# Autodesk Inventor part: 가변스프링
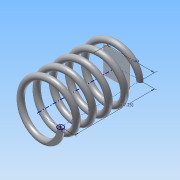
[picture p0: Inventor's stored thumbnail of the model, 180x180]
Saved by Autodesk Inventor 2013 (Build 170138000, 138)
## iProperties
Created: 2018-08
Part Number: 가변스프링
Material: 알루미늄 6061
Document SubType Name: Modeling
Designer: Administrator
Density: 2.71 g/cm^3
Mass: 32.8823 g
Surface Area: 98.6263 cm^2
Volume: 12.1337 cm^3
Author: Administrator
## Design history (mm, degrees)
sketch "스케치1"
  geometry: L1 (0, 0)-(20, 0); L2 (20, 0)-(20, 67.25); L3 (20, 67.25)-(0, 67.25); L4 (0, 67.25)-(0, 0); C1 r 2.5 at (20, 0)
  constraints: 8 end point, 2 parallel, 1 centre point, 1 coincident, 1 horizontal, 1 perpendicular
  dimensions: "d0" = 5 diameter of C1; "d2" = 67.25 distance between parallel lines of L3 L1 (derived); "d3" = 40 diameter of L2 L4
feature "코일1" pitch "d4" = 10; turns "d6" = 5; dims "d5" = 67.25 (= d2), "d7" = 0, angle "d8" = 90 deg, angle "d9" = 90 deg, "d10" = 0, "d11" = 0
sketch "스케치2"
  geometry: L1 (-22.5, 0)-(-17.5, 0) reference; 1 further point
  constraints: 1 horizontal alignment
extrude "돌출1" cut sketch "스케치2" stored distance "d12" = 10; taper "d13" = 0 deg
node "작업 평면1"
sketch "스케치3"
  geometry: L1 (22.5, 0)-(17.5, 0) reference; 1 further point
  constraints: 1 horizontal alignment
extrude "돌출2" cut sketch "스케치3" stored distance "d14" = 10; taper "d15" = 0 deg
node "솔리드1"
node "절단 모서리 투영1"
node "절단 모서리 투영2"
